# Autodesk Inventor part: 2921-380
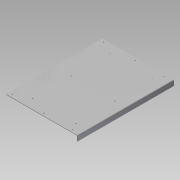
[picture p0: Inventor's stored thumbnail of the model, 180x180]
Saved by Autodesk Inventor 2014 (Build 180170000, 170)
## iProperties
Company: NHTSA/VRTC
Created: 2012-02
Part Number: 2921-380
Project: CHILD SIDE IMPACT SLED
Material: Steel
Description: BENCH SEAT BACK PANEL
Document SubType Name: Modeling
Designer: Mike Vanvoorhis
Mass: 9786.19 g
Surface Area: 7882.07 cm^2
Volume: 1246.65 cm^3
Density: 7.85 g/cm^3
Appearance: Steel
Stock Number: PL 3.2 (1/8") x 552.8 (21 3/4") x 700.0 (27 9/16")
Title: Bench Seat Back Panel
Subject: Child Side Impact Sled
Author: Dave Walker
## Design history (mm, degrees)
sketch "Sketch1"
  geometry: L1 (-520, 0)-(-6.4, 0); L2 (-6.4, -3.2)-(-520, -3.2); L3 (-520, -3.2)-(-520, 0); L4 (-3.2, -38.1)-(0, -38.1); L5 (0, -38.1)-(0, -6.4); L6 (-3.2, -6.4)-(-3.2, -38.1); L7 (0, 9.211)-(0, -45.985) reference; L8 (-624.265, 0)-(105.591, 0) reference; A1 r 3.2 centre (-6.4, -6.4) between (-3.2, -6.4) and (-6.4, -3.2); A2 r 6.4 centre (-6.4, -6.4) between (0, -6.4) and (-6.4, 0); 1 further point
  constraints: 12 end point, 4 point on circle, 4 tangent, 2 centre point, 2 collinear, 2 parallel, 2 perpendicular, 2 point on line, 1 horizontal
  dimensions: "d0" = 520 distance of L1.start point (0, 0); "d1" = 38.1 distance of L4.end point (0, 0); "d2" = 3.2 distance of L4.start L4.end; "d3" = 3.2 distance of L2.end L1.start (= d2); "d4" = 3.2 radius of A1; "d5" = 6.4 radius of A2
extrude "Extrusion1" new body sketch "Sketch1" stored distance "d6" = 700; taper "d7" = 0 deg
sketch "Sketch2"
  geometry: L1 (520, 0)-(520, 700) reference; L2 (0, 0)-(513.6, 0) reference; 6 further points
  constraints: 3 horizontal alignment
  dimensions: "d8" = 56 distance from line of point (464, 19.038) L1; "d16" = 19.038 distance from line of point (464, 19.038) L2; "d25" = 262 distance from line of point (258, 19.038) L1; "d26" = 492.6 distance from line of point (27.4, 19.038) L1; "d27" = 81 distance from line of point (439, 70) L1; "d28" = 396 distance from line of point (124, 70) L1; "d36" = 70 distance from line of point (439, 70) L2
hole "Hole1" sketch "Sketch2" at (464, 19.038), (439, 70), (258, 19.038), (124, 70), (27.4, 19.038) diameter "d18" = 7.1374; stored, may be unused: countersink angle "d22" = 90 deg, drill point angle "d24" = 118 deg; dims "d19" = 6, "d20" = 4, "d21" = 2, "d23" = 8
mirror "Mirror1"
sketch "Sketch3"
  geometry: C1 r 3.569 at (124, 70) reference; C2 r 3.569 at (439, 70) reference; 3 further points
  constraints: 2 horizontal alignment, 2 vertical alignment
hole "Hole2" sketch "Sketch3" at (439, 350), (124, 350) diameter "d29" = 7.1374; stored, may be unused: countersink angle "d33" = 90 deg, drill point angle "d35" = 118 deg; dims "d30" = 6, "d31" = 4, "d32" = 2, "d34" = 8
body "Solid1"
